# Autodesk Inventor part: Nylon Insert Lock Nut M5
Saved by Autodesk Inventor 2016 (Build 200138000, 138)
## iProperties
Created: 2015-11
Part Number: Nylon Insert Lock Nut M5
Material: Generic
Document SubType Name: Modeling
Designer: John
Density: 1 g/cm^3
Appearance: Default
Author: John
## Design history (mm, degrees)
feature "SOLID1"
body "Solid1"
